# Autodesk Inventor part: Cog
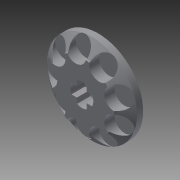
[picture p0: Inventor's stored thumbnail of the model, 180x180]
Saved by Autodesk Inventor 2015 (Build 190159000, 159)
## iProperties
Created: 2015-09
Part Number: Cog
Material: Generic
Document SubType Name: Modeling
Designer: Thomas
Density: 1 g/cm^3
Appearance: Default
Author: Thomas
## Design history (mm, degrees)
sketch "Sketch1"
  geometry: L1 (15.4, 0)-(-15.4, 0) reference; L2 (0, -15.4)-(0, 15.4) reference; C1 r 11 at (0, 0); C2 r 2.5 at (8.5, 0); C3 r 2.5 at (6.511, 5.464); C4 r 2.5 at (1.476, 8.371); C5 r 2.5 at (-4.25, 7.361); C6 r 2.5 at (-7.987, 2.907); C7 r 2.5 at (-7.987, -2.907); C8 r 2.5 at (-4.25, -7.361); C9 r 2.5 at (1.476, -8.371); C10 r 2.5 at (6.511, -5.464); 1 further point
  constraints: 10 centre point, 1 coincident, 1 point on line, 19 other
  dimensions: "d0" = 22 diameter of C1; "d1" = 5 diameter of C2; "d2" = 8.5 distance from line of L2 C2.centre; "d5" = 360 deg dimension on point (0, 0) C2.centre (derived)
extrude "Extrusion2" new body sketch "Sketch1" distance "d11" = 5; taper "d12" = 0 deg
sketch "Sketch2"
  geometry: C1 r 11 at (0, 0); 1 further point
  constraints: 1 centre point
  dimensions: "d13" = 22 diameter of C1
extrude "Extrusion3" join sketch "Sketch2" distance "d14" = 1.5; taper "d15" = 0 deg
sketch "Sketch3"
  geometry: C1 r 11 at (6.511, 5.464); 1 further point
  constraints: 1 centre point
extrude "Extrusion4" join sketch "Sketch3" distance "d16" = 1.5; taper "d17" = 0 deg
workplane "Work Plane2"
  workplane "Work Plane1"
sketch "Sketch4"
  geometry: L1 (11, -1.5)-(11, 6.5) reference; L2 (-11, -1.5)-(11, -1.5) reference; L3 (11, 6.5)-(-11, 6.5) reference; L4 (11, 0)-(11, 5); L5 (11, 5)-(7.5, 2.5); L6 (7.5, 2.5)-(11, 0); L7 (0, -3.1)-(0, 8.1) reference; 3 further points
  constraints: 6 end point, 2 point on line
  dimensions: "d19" = 5 distance of L4.start L4.end; "d21" = 3.5 distance from line of L5.end L1; "d22" = 4 distance from line of L5.end L2
revolve "Revolution1" sketch "Sketch4" stored, may be unused: angle "d23" = 90 deg
fillet "Fillet1" dims "d24" = 0.5
sketch "Sketch5"
  geometry: L1 (3, -1.2)-(3, 1.2); L2 (-3, 1.2)-(-3, -1.2); L3 (0, 15.4)-(0, -15.4) reference; L4 (-15.403, 0)-(15.4, 0) reference; L5 (-1.2, -3)-(1.2, -3); L6 (1.2, 3)-(-1.2, 3); L7 (-1.2, 3)-(-1.2, 1.2); L8 (-1.2, -1.2)-(-1.2, -3); L9 (1.2, -3)-(1.2, -1.2); L10 (1.2, 1.2)-(1.2, 3); L11 (3, 1.2)-(1.2, 1.2); L12 (-1.2, 1.2)-(-3, 1.2); L13 (-3, -1.2)-(-1.2, -1.2); L14 (1.2, -1.2)-(3, -1.2); A1 r 2.8 centre (0, 0) between (-2.53, 1.2) and (-2.53, -1.2); A2 r 2.8 centre (0, 0) between (-1.2, -2.53) and (1.2, -2.53); A3 r 2.8 centre (0, 0) between (2.53, -1.2) and (2.53, 1.2); A4 r 2.8 centre (0, 0) between (1.2, 2.53) and (-1.2, 2.53); 9 further points
  constraints: 24 end point, 16 point on line, 10 parallel, 8 point on circle, 4 centre point, 4 perpendicular, 3 horizontal, 1 coincident
  dimensions: "d26" = 6 distance of L2.start L1.end; "d27" = 2.4 distance of L1.end L1.start; "d29" = 2.4 distance of L6.end L6.start; "d30" = 6 distance of L6.start L5.end; "d38" = 1.2 distance between parallel lines of L4 L14; "d39" = 1.2 distance between parallel lines of L3 L10; "d40" = 1.2 distance between parallel lines of L3 L9; "d41" = 1.2 distance between parallel lines of L4 L12; "d42" = 2.4 distance between parallel lines of L13 L12; "d43" = 2.4 distance between parallel lines of L9 L8; "d46" = 3 distance between parallel lines of L4 L5; "d47" = 3 distance between parallel lines of L3 L1; "d49" = 2.8 radius of A1; "d50" = 2.8 radius of A3; "d51" = 2.8 radius of A4; "d52" = 2.8 radius of A2
extrude "Extrusion5" cut sketch "Sketch5" distance "d32" = 8; taper "d33" = 0 deg
sketch "Sketch6"
  geometry: C1 r 11 at (0, 0); 1 further point
  constraints: 1 centre point, 1 coincident
extrude "Extrusion6" cut sketch "Sketch6" distance "d35" = 4; taper "d36" = 0 deg
fillet "Fillet4" dims "d48" = 1
body "Solid2"
other parameters: "d18" = -11, "d25" = 5, "d28" = 1, "d31" = 1, "d45" = 5.2
